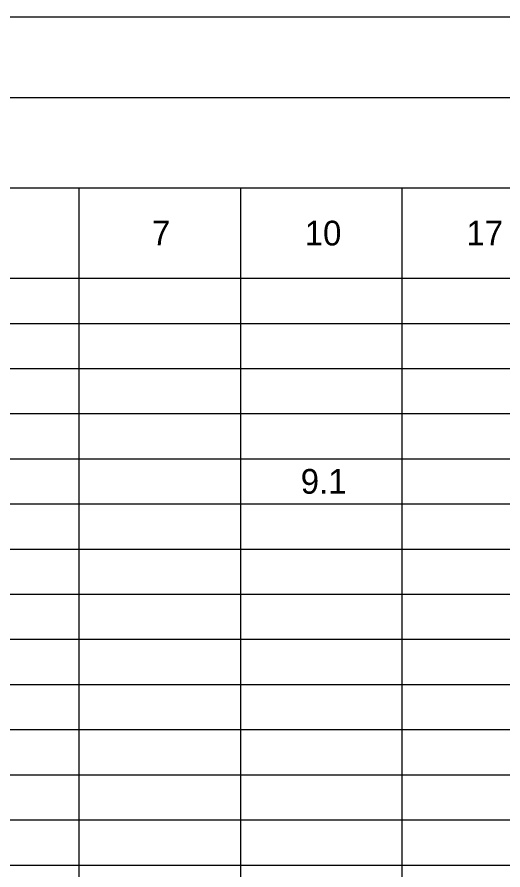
# Model space of a CAD drawing. Extents: x 0 to 34, y 0 to 22.
# Drawn here: x 3.12 to 6.14, y 16.71 to 22 of the extents above; entities that cross this region are included whole.
import ezdxf

# ---------------------------------------------------------------- set-up
doc = ezdxf.new("R2010")
doc.units = 0
for name, color, linetype in [('Default', 7, 'Continuous'), ('SH_Border', 7, 'Continuous'), ('SH_Cut_Line', 7, 'Continuous')]:
    doc.layers.add(name, color=color, linetype=linetype)

msp = doc.modelspace()

# ---------------------------------------------------------------- linework, layer by layer
at = {"layer": 'Default'}
for p, q in [((1.5, 21.5), (6.5126, 21.5)), ((1.5, 20.94), (6.5126, 20.94)), ((3.5051, 20.94), (3.5051, 20.66)), ((4.5076, 20.94), (4.5076, 20.66)), ((5.5101, 20.94), (5.5101, 20.66)), ((3.5051, 20.66), (3.5051, 20.38)), ((4.5076, 20.66), (4.5076, 20.38)), ((5.5101, 20.66), (5.5101, 20.38)), ((1.5, 20.38), (6.5126, 20.38)), ((3.5051, 20.38), (3.5051, 20.1)), ((4.5076, 20.38), (4.5076, 20.1)), ((5.5101, 20.38), (5.5101, 20.1)), ((1.5, 20.1), (6.5126, 20.1)), ((3.5051, 20.1), (3.5051, 18.7)), ((4.5076, 20.1), (4.5076, 18.7)), ((5.5101, 20.1), (5.5101, 18.7)), ((1.5, 19.82), (6.5126, 19.82)), ((1.5, 19.54), (6.5126, 19.54)), ((1.5, 19.26), (6.5126, 19.26)), ((1.5, 18.98), (6.5126, 18.98)), ((1.5, 18.7), (6.5126, 18.7)), ((3.5051, 18.7), (3.5051, 18.14)), ((4.5076, 18.7), (4.5076, 18.14)), ((5.5101, 18.7), (5.5101, 18.14)), ((1.5, 18.42), (6.5126, 18.42)), ((1.5, 18.14), (6.5126, 18.14)), ((3.5051, 18.14), (3.5051, 17.86)), ((4.5076, 18.14), (4.5076, 17.86)), ((5.5101, 18.14), (5.5101, 17.86)), ((1.5, 17.86), (6.5126, 17.86)), ((3.5051, 17.86), (3.5051, 17.58)), ((4.5076, 17.86), (4.5076, 17.58)), ((5.5101, 17.86), (5.5101, 17.58)), ((1.5, 17.58), (6.5126, 17.58)), ((3.5051, 17.58), (3.5051, 17.3)), ((4.5076, 17.58), (4.5076, 17.3)), ((5.5101, 17.58), (5.5101, 17.3)), ((1.5, 17.3), (6.5126, 17.3)), ((3.5051, 17.3), (3.5051, 17.02)), ((4.5076, 17.3), (4.5076, 17.02)), ((5.5101, 17.3), (5.5101, 17.02)), ((1.5, 17.02), (6.5126, 17.02)), ((3.5051, 17.02), (3.5051, 16.74)), ((4.5076, 17.02), (4.5076, 16.74)), ((5.5101, 17.02), (5.5101, 16.74)), ((1.5, 16.74), (6.5126, 16.74)), ((3.5051, 16.74), (3.5051, 16.18)), ((4.5076, 16.74), (4.5076, 16.18)), ((5.5101, 16.74), (5.5101, 16.18))]:
    msp.add_line(p, q, dxfattribs=at)
at = {"layer": 'SH_Border'}
msp.add_lwpolyline([(1.5, 21.5), (33.5, 21.5), (33.5, 0.5), (1.5, 0.5)], close=True, dxfattribs=at)
at = {"layer": 'SH_Cut_Line'}
msp.add_lwpolyline([(0, 0), (34, 0), (34, 22), (0, 22)], close=True, dxfattribs=at)

# ---------------------------------------------------------------- texts
at = {"layer": 'Default'}
for s, height, p in [('10', 0.15333, (4.9063, 20.5833)), ('7', 0.1533, (3.958, 20.5833)), ('17', 0.15333, (5.91, 20.5833)), ('9.1', 0.15333, (4.8819, 19.0433))]:
    msp.add_text(s, height=height, dxfattribs=at).set_placement(p)

doc.saveas('drawing.dxf')
